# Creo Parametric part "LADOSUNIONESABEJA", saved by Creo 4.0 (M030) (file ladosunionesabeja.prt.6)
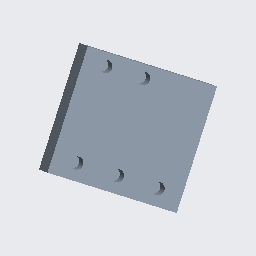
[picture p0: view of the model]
Units: millimeter Newton Second (mmNs); MM, TONNE, SECS

Created from: MMNS_PART_SOLID.PRT

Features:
  1. datum plane "RIGHT"
  2. datum plane "TOP"
  3. datum plane "FRONT"
  4. coordinate system
  5. sketch "Sketch 1"
  6. extrusion "Extrude 1"
  7. pattern "Pattern 1"
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
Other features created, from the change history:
  hole "Hole 1"
  hole "Hole 1 [2]"
  hole "Hole 1 [3]"
  hole "Hole 2"
  pattern "Patrón 2"
  hole "Taladro 2 [2]"
  hole "Hole 3"
  pattern "Pattern 3"
  hole "Hole 3 [2]"

Surfaces: 13 plane, 7 cylinder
